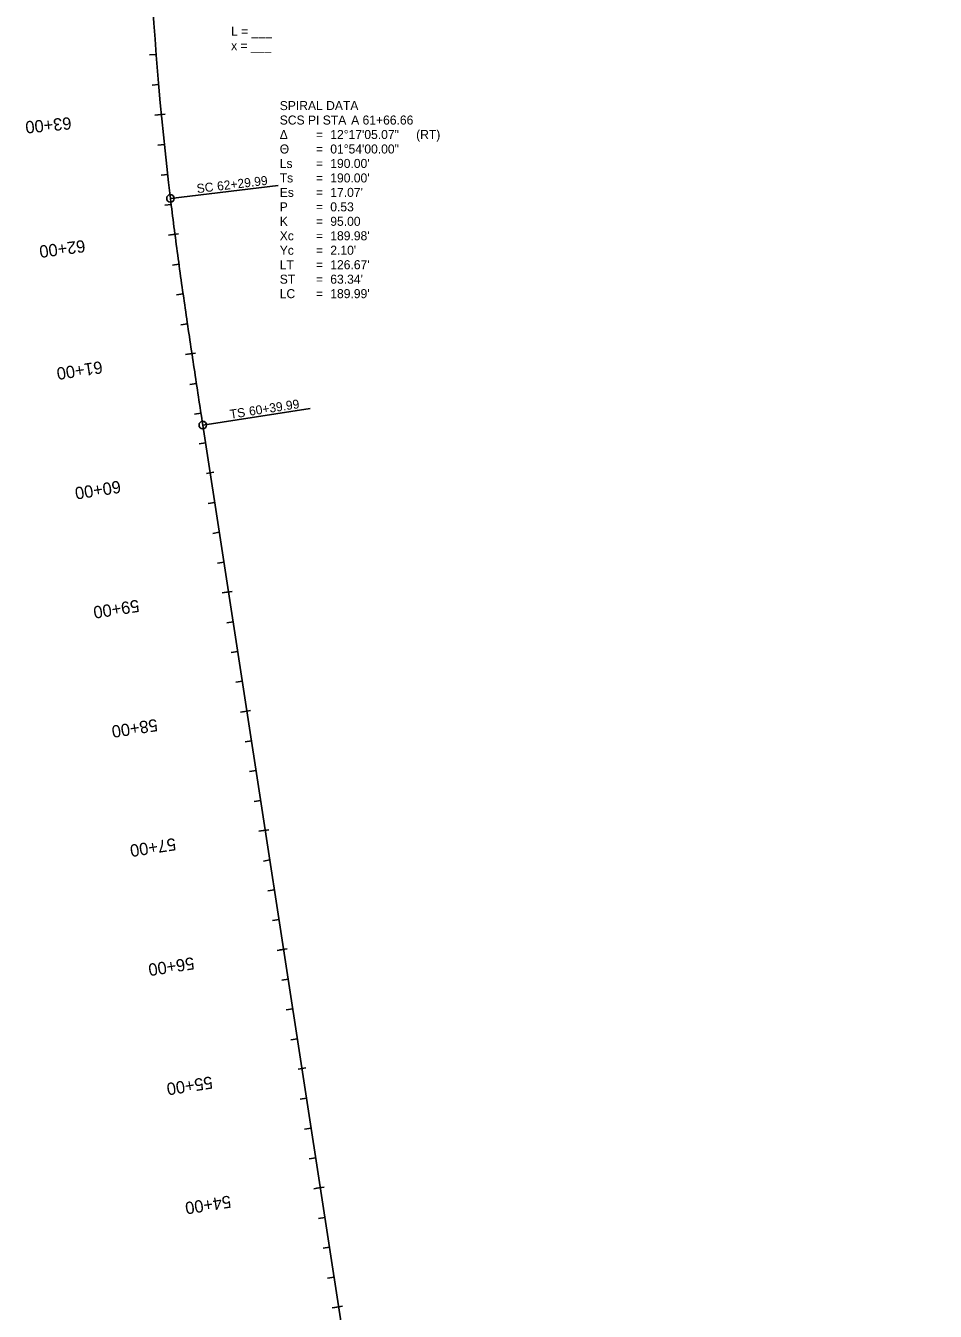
# Model space of a CAD drawing. Extents: x 11526485 to 11527255, y 9590594 to 9599170.
# Drawn here: x 11526498 to 11527252, y 9593816 to 9594882 of the extents above; entities that cross this region are included whole.
import ezdxf

# ---------------------------------------------------------------- set-up
doc = ezdxf.new("R2010")
doc.units = 0
for name, color, linetype in [('Alignment', 7, 'Continuous'), ('Default', 7, 'Continuous'), ('TextAlignment', 7, 'Continuous'), ('TextAlignmentLrg', 7, 'Continuous'), ('TextAlignmentSml', 7, 'Continuous')]:
    doc.layers.add(name, color=color, linetype=linetype)

msp = doc.modelspace()

# ---------------------------------------------------------------- linework, layer by layer
at = {"layer": 'Alignment'}
msp.add_line((11527252.3, 9590607.6), (11526645, 9594551), dxfattribs=at)
msp.add_arc((11529462.5, 9595081), 2864.8, 178.3695, 186.8543, dxfattribs=at)
msp.add_open_spline([(11526645, 9594551), (11526642.6, 9594566.7), (11526637.8, 9594598), (11526630.8, 9594644.9), (11526624.1, 9594692), (11526620.1, 9594723.4), (11526618.2, 9594739.1)], degree=3, dxfattribs=at)
at = {"layer": 'Default'}
msp.add_line((11527252.3, 9590607.6), (11526645, 9594551), dxfattribs=at)
msp.add_arc((11529462.5, 9595081), 2864.8, 178.3695, 186.8543, dxfattribs=at)
msp.add_open_spline([(11526645, 9594551), (11526642.6, 9594566.7), (11526637.8, 9594598), (11526630.8, 9594644.9), (11526624.1, 9594692), (11526620.1, 9594723.4), (11526618.2, 9594739.1)], degree=3, dxfattribs=at)
at = {"layer": 'TextAlignment'}
for p, q in [((11526618.2, 9594739.1), (11526707.6, 9594749.8)), ((11526618.2, 9594739.1), (11526707.6, 9594749.8)), ((11526707.6, 9594749.8), (11526707.6, 9594749.8)), ((11526707.6, 9594749.8), (11526707.6, 9594749.8)), ((11526645, 9594551), (11526734, 9594564.7)), ((11526734, 9594564.7), (11526734, 9594564.7))]:
    msp.add_line(p, q, dxfattribs=at)
for centre in [(11526618.2, 9594739.1), (11526618.2, 9594739.1), (11526645, 9594551)]:
    msp.add_circle(centre, 3.12, dxfattribs=at)
at = {"layer": 'TextAlignmentLrg'}
for p, q in [((11526610.7, 9594808.7), (11526605.3, 9594808.2)), ((11526621.9, 9594709.3), (11526616.5, 9594708.6)), ((11526636, 9594610.3), (11526630.6, 9594609.5)), ((11526648.1, 9594511), (11526654.2, 9594512)), ((11526666.4, 9594412.7), (11526661, 9594411.8)), ((11526681.6, 9594313.8), (11526676.2, 9594313)), ((11526696.8, 9594215), (11526691.4, 9594214.1)), ((11526712, 9594116.1), (11526706.6, 9594115.3)), ((11526724.2, 9594016.8), (11526730.3, 9594017.8)), ((11526742.5, 9593918.5), (11526737.1, 9593917.6)), ((11526757.7, 9593819.6), (11526752.3, 9593818.8))]:
    msp.add_line(p, q, dxfattribs=at)
at = {"layer": 'TextAlignmentSml'}
for p, q in [((11526606.4, 9594858.5), (11526600.9, 9594858.1)), ((11526608.4, 9594833.6), (11526603, 9594833.1)), ((11526607.7, 9594808.4), (11526613.8, 9594809)), ((11526613.2, 9594783.8), (11526607.8, 9594783.3)), ((11526615.9, 9594759), (11526610.5, 9594758.4)), ((11526618.8, 9594734.1), (11526613.4, 9594733.5)), ((11526618.9, 9594708.9), (11526625, 9594709.7)), ((11526625.2, 9594684.6), (11526619.8, 9594683.8)), ((11526628.7, 9594659.8), (11526623.3, 9594659)), ((11526632.3, 9594635.1), (11526626.9, 9594634.3)), ((11526633, 9594609.9), (11526639, 9594610.8)), ((11526639.7, 9594585.6), (11526634.3, 9594584.8)), ((11526643.5, 9594560.9), (11526638.1, 9594560.1)), ((11526647.3, 9594536.2), (11526641.9, 9594535.4)), ((11526648.1, 9594511), (11526654.2, 9594512)), ((11526654.9, 9594486.8), (11526649.5, 9594485.9)), ((11526658.7, 9594462.1), (11526653.3, 9594461.2)), ((11526662.6, 9594437.4), (11526657.2, 9594436.5)), ((11526663.3, 9594412.2), (11526669.4, 9594413.1)), ((11526670.2, 9594387.9), (11526664.8, 9594387.1)), ((11526674, 9594363.2), (11526668.6, 9594362.4)), ((11526677.8, 9594338.5), (11526672.4, 9594337.7)), ((11526678.6, 9594313.3), (11526684.6, 9594314.3)), ((11526685.4, 9594289.1), (11526680, 9594288.3)), ((11526689.2, 9594264.4), (11526683.8, 9594263.6)), ((11526693, 9594239.7), (11526687.6, 9594238.9)), ((11526693.8, 9594214.5), (11526699.8, 9594215.4)), ((11526700.6, 9594190.3), (11526695.2, 9594189.4)), ((11526704.4, 9594165.6), (11526699, 9594164.7)), ((11526708.2, 9594140.9), (11526702.8, 9594140)), ((11526709, 9594115.7), (11526715, 9594116.6)), ((11526715.8, 9594091.4), (11526710.4, 9594090.6)), ((11526719.6, 9594066.7), (11526714.2, 9594065.9)), ((11526723.4, 9594042), (11526718, 9594041.2)), ((11526724.2, 9594016.8), (11526730.3, 9594017.8)), ((11526731, 9593992.6), (11526725.6, 9593991.8)), ((11526734.8, 9593967.9), (11526729.4, 9593967.1)), ((11526738.6, 9593943.2), (11526733.3, 9593942.4)), ((11526739.4, 9593918), (11526745.5, 9593918.9)), ((11526746.3, 9593893.8), (11526740.9, 9593892.9)), ((11526750.1, 9593869.1), (11526744.7, 9593868.2)), ((11526753.9, 9593844.3), (11526748.5, 9593843.5)), ((11526754.6, 9593819.2), (11526760.7, 9593820.1))]:
    msp.add_line(p, q, dxfattribs=at)

# ---------------------------------------------------------------- texts
at = {"layer": 'TextAlignment'}
for s, p in [('L = ___', (11526668.5, 9594874)), ('x = ___', (11526668.5, 9594862)), ('SPIRAL DATA', (11526708.8, 9594812.3)), ('SCS PI STA ', (11526708.8, 9594800.3)), ('A 61+66.66', (11526768, 9594800.3)), ('Δ', (11526708.8, 9594788.3)), ('= ', (11526738.8, 9594788.3)), ('12°17\'05.07"', (11526750.7, 9594788.3)), (' (RT)', (11526819.1, 9594788.3)), ('Θ ', (11526708.8, 9594776.3)), ('01°54\'00.00"', (11526750.7, 9594776.3)), ('= ', (11526738.8, 9594776.3)), ('Ls', (11526708.8, 9594764.3)), ('= ', (11526738.8, 9594764.3)), ("190.00'", (11526750.7, 9594764.3)), ('Ts', (11526708.8, 9594752.3)), ('= ', (11526738.8, 9594752.3)), ("190.00'", (11526750.7, 9594752.3)), ('Es', (11526708.8, 9594740.3)), ('= ', (11526738.8, 9594740.3)), ("17.07'", (11526750.7, 9594740.3)), ('P', (11526708.8, 9594728.3)), ('= ', (11526738.8, 9594728.3)), ('0.53', (11526750.7, 9594728.3)), ('K', (11526708.8, 9594716.3)), ('= ', (11526738.8, 9594716.3)), ('95.00', (11526750.7, 9594716.3)), ('Xc', (11526708.8, 9594704.3)), ('= ', (11526738.8, 9594704.3)), ("189.98'", (11526750.7, 9594704.3)), ('Yc', (11526708.8, 9594692.3)), ('= ', (11526738.8, 9594692.3)), ("2.10'", (11526750.7, 9594692.3)), ('LT', (11526708.8, 9594680.3)), ("126.67'", (11526750.7, 9594680.3)), ('= ', (11526738.8, 9594680.3)), ('ST ', (11526708.8, 9594668.3)), ('= ', (11526738.8, 9594668.3)), ("63.34'", (11526750.7, 9594668.3)), ('LC', (11526708.8, 9594656.3)), ('= ', (11526738.8, 9594656.3)), ("189.99'", (11526750.7, 9594656.3))]:
    msp.add_text(s, height=7.5, dxfattribs=at).set_placement(p)
for s, rotation, p in [('SC', 6.8543, (11526640.4, 9594743.4)), ('SC', 6.8543, (11526640.4, 9594743.4)), ('62+29.99', 6.8543, (11526657.3, 9594745.4)), ('62+29.99', 6.8543, (11526657.3, 9594745.4)), ('60+39.99', 8.7543, (11526683.9, 9594558.7)), ('TS', 8.7543, (11526668, 9594556.2))]:
    msp.add_text(s, height=7.5, rotation=rotation, dxfattribs=at).set_placement(p)
at = {"layer": 'TextAlignmentLrg'}
for s, p in [('60+00', (11526576.2, 9594505.1)), ('55+00', (11526652.3, 9594010.9))]:
    msp.add_text(s, height=10.2, rotation=188.7543, dxfattribs=at).set_placement(p)
at = {"layer": 'TextAlignmentSml'}
for s, rotation, p in [('63+00', 185.4541, (11526535.6, 9594806.6)), ('62+00', 187.4067, (11526546.9, 9594704.7)), ('61+00', 188.5647, (11526561.1, 9594604.2)), ('60+00', 188.7543, (11526576.2, 9594505.1)), ('59+00', 188.7543, (11526591.5, 9594406.3)), ('58+00', 188.7543, (11526606.7, 9594307.4)), ('57+00', 188.7543, (11526621.9, 9594208.6)), ('56+00', 188.7543, (11526637.1, 9594109.8)), ('55+00', 188.7543, (11526652.3, 9594010.9)), ('54+00', 188.7543, (11526667.6, 9593912.1))]:
    msp.add_text(s, height=10.2, rotation=rotation, dxfattribs=at).set_placement(p)

doc.saveas('drawing.dxf')
